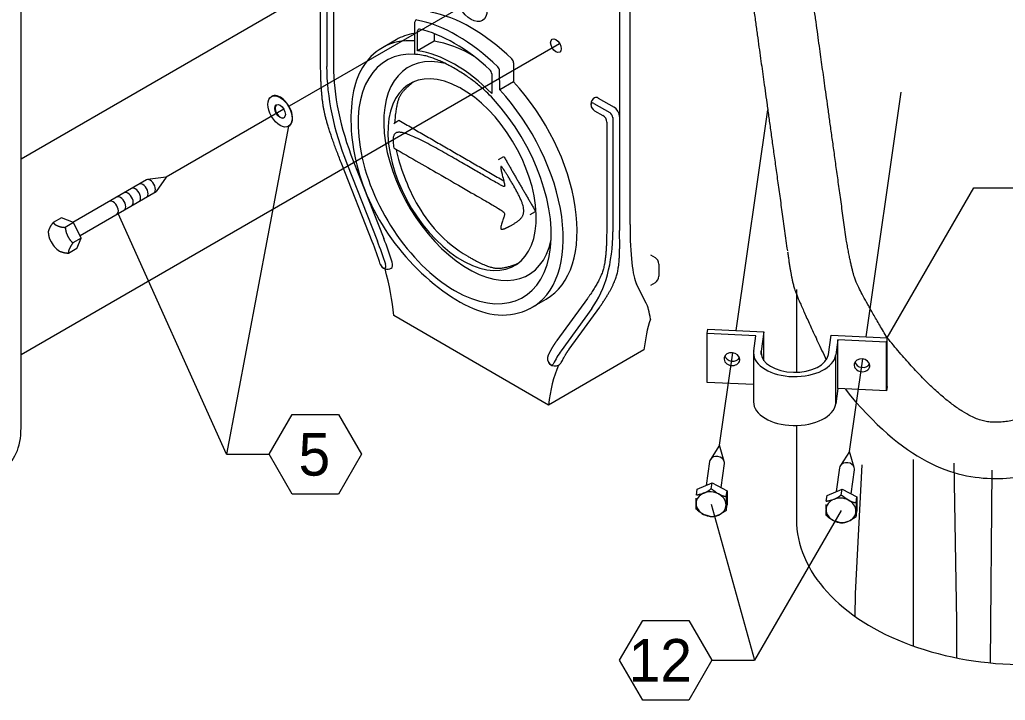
# Model space of a CAD drawing. Extents: x 99862 to 103151, y 100000 to 105076.
# Drawn here: x 101157.1 to 101527.1, y 103346.2 to 103601.7 of the extents above; entities that cross this region are included whole.
import ezdxf

# ---------------------------------------------------------------- set-up
doc = ezdxf.new("R2010")
doc.units = 0
for name, color, linetype in [('Level 15', 7, 'Continuous'), ('Level 16', 7, 'Continuous'), ('Level 20', 7, 'Continuous'), ('Level 28', 7, 'Continuous'), ('Level 31', 7, 'Continuous'), ('Level 33', 7, 'Continuous'), ('Level 34', 7, 'Continuous'), ('Level 35', 7, 'Continuous'), ('Level 36', 7, 'Continuous'), ('Level 38', 7, 'Continuous'), ('Level 41', 7, 'Continuous'), ('Level 42', 7, 'Continuous')]:
    doc.layers.add(name, color=color, linetype=linetype)

msp = doc.modelspace()

# ---------------------------------------------------------------- linework, layer by layer
at = {"layer": 'Level 15'}
for p, q in [((101258.03, 103561.71), (101234.74, 103438.58)), ((101482.7, 103482.36), (101515.2, 103538.65)), ((101515.2, 103538.65), (101531.2, 103538.65)), ((101234.74, 103438.58), (101194.04, 103528.95)), ((101234.74, 103438.58), (101250.74, 103438.58)), ((101416.61, 103419.87), (101432.9, 103361.25)), ((101465.4, 103417.54), (101432.9, 103361.25)), ((101416.9, 103361.25), (101432.9, 103361.25))]:
    msp.add_line(p, q, dxfattribs=at)
at = {"layer": 'Level 16'}
for p, q in [((101157.59, 103549.52), (101296.13, 103629.51)), ((101330.41, 103610.93), (101258.17, 103569.23)), ((101157.59, 103476.04), (101359.77, 103592.77)), ((101474.77, 103482.74), (101487.95, 103574.52)), ((101256.22, 103568.1), (101212, 103542.57)), ((101425.97, 103485.07), (101437.88, 103567.94)), ((101419.78, 103441.97), (101424.77, 103476.71)), ((101468.58, 103439.63), (101473.57, 103474.38))]:
    msp.add_line(p, q, dxfattribs=at)
at = {"layer": 'Level 20'}
for points in [[(101250.74, 103438.58), (101259.4, 103453.57), (101276.72, 103453.57), (101285.37, 103438.58), (101276.72, 103423.58), (101259.4, 103423.58), (101250.74, 103438.58)], [(101382.28, 103361.25), (101390.94, 103376.24), (101408.26, 103376.24), (101416.9, 103361.25), (101408.26, 103346.25), (101390.94, 103346.25), (101382.28, 103361.25)]]:
    msp.add_lwpolyline(points, dxfattribs=at)
at = {"layer": 'Level 28'}
for p, q in [((101415.19, 103483.96), (101415.43, 103485.58)), ((101415.43, 103485.58), (101436.45, 103484.57)), ((101433.41, 103483.09), (101415.19, 103483.96)), ((101415.19, 103465.59), (101415.19, 103483.96)), ((101432.6, 103477.42), (101433.41, 103483.09)), ((101436.45, 103484.57), (101435.4, 103477.29)), ((101436.45, 103473.72), (101436.45, 103484.57)), ((101460.63, 103476.08), (101461.67, 103483.36)), ((101461.67, 103483.36), (101482.7, 103482.36)), ((101482.7, 103482.36), (101482.46, 103480.74)), ((101482.7, 103463.99), (101482.7, 103482.36)), ((101464.24, 103481.61), (101463.43, 103475.95)), ((101482.46, 103480.74), (101464.24, 103481.61)), ((101464.24, 103463.24), (101464.24, 103481.61)), ((101482.46, 103462.37), (101482.46, 103480.74)), ((101432.55, 103476.69), (101432.55, 103458.31)), ((101435.4, 103476.08), (101435.4, 103477.29)), ((101463.43, 103457.58), (101463.43, 103475.95)), ((101432.55, 103464.76), (101415.19, 103465.59)), ((101482.7, 103463.99), (101482.46, 103462.37)), ((101464.24, 103463.24), (101463.43, 103457.58)), ((101482.46, 103462.37), (101464.24, 103463.24)), ((101419.78, 103441.97), (101416.36, 103436.66)), ((101421.58, 103435.91), (101419.78, 103441.97)), ((101468.58, 103439.63), (101465.15, 103434.32)), ((101470.37, 103433.58), (101468.58, 103439.63)), ((101416.07, 103435.89), (101414.78, 103426.91)), ((101420.35, 103426.1), (101421.64, 103435.09)), ((101464.86, 103433.56), (101463.57, 103424.57)), ((101469.14, 103423.77), (101470.43, 103432.76)), ((101411.39, 103425.47), (101416.99, 103427.85)), ((101416.68, 103425.68), (101416.99, 103427.85)), ((101416.99, 103427.85), (101422.6, 103424.93)), ((101411.08, 103423.29), (101411.39, 103425.47)), ((101422.29, 103422.76), (101422.6, 103424.93)), ((101422.6, 103424.93), (101422.6, 103419.63)), ((101459.87, 103420.96), (101460.18, 103423.13)), ((101460.18, 103423.13), (101465.79, 103425.51)), ((101465.48, 103423.34), (101465.79, 103425.51)), ((101465.79, 103425.51), (101471.39, 103422.59)), ((101422.29, 103417.45), (101422.6, 103419.63)), ((101471.08, 103420.42), (101471.39, 103422.59)), ((101471.39, 103422.59), (101471.39, 103417.29)), ((101471.08, 103415.12), (101471.39, 103417.29))]:
    msp.add_line(p, q, dxfattribs=at)
for centre, major_axis, ratio, start_param, end_param in [((101424.43, 103474.33), (2.92, -0.42), 0.813704, 3.141593, 6.283185), ((101424.43, 103474.33), (2.92, -0.42), 0.813704, 0.116344, 3.141593), ((101424.66, 103475.95), (-2.92, 0.42), 0.813704, 0.346937, 2.794655), ((101448.02, 103476.69), (15.47, 0), 0.57735, 3.058857, 3.141593), ((101448.02, 103476.69), (15.47, 0), 0.57735, 3.141593, 6.20045), ((101448.02, 103476.69), (-12.66, 0), 0.57735, 6.20045, 6.283185), ((101448.02, 103476.69), (-12.66, 0), 0.57735, 0, 3.058857), ((101473.23, 103472), (2.92, -0.42), 0.813704, 0.116344, 3.141593), ((101424.43, 103474.33), (2.92, -0.42), 0.813704, 0, 0.116344), ((101473.23, 103472), (2.92, -0.42), 0.813704, 3.141593, 6.283185), ((101473.46, 103473.61), (-2.92, 0.42), 0.813704, 0.346937, 2.794655), ((101473.23, 103472), (2.92, -0.42), 0.813704, 6.283185, 6.399529), ((101448.02, 103458.31), (15.47, 0), 0.57735, 3.141593, 6.20045), ((101418.85, 103435.49), (-2.78, 0.4), 0.813704, 3.499123, 5.925655), ((101418.85, 103435.49), (-2.78, 0.4), 0.813704, 5.925655, 6.283185), ((101418.85, 103435.49), (-2.78, 0.4), 0.813704, 3.141593, 3.499123), ((101467.65, 103433.16), (-2.78, 0.4), 0.813704, 5.925655, 6.283185), ((101467.65, 103433.16), (-2.78, 0.4), 0.813704, 3.499123, 5.925655), ((101467.65, 103433.16), (-2.78, 0.4), 0.813704, 3.141593, 3.499123), ((101416.61, 103419.87), (-5.57, 0.8), 0.813704, 5.352332, 6.399529), ((101416.61, 103419.87), (-5.57, 0.8), 0.813704, 4.305134, 5.352332), ((101416.61, 103419.87), (-5.57, 0.8), 0.813704, 3.257937, 4.305134), ((101416.61, 103419.87), (5.57, -0.8), 0.813704, 3.257937, 4.305134), ((101416.61, 103419.87), (-5.57, 0.8), 0.813704, 2.210739, 3.257937), ((101465.4, 103417.54), (-5.57, 0.8), 0.813704, 5.352332, 6.399529), ((101465.4, 103417.54), (-5.57, 0.8), 0.813704, 4.305134, 5.352332), ((101465.4, 103417.54), (-5.57, 0.8), 0.813704, 3.257937, 4.305134), ((101416.61, 103419.87), (-5.57, 0.8), 0.813704, 1.163542, 2.210739), ((101465.4, 103417.54), (5.57, -0.8), 0.813704, 3.257937, 4.305134), ((101465.4, 103417.54), (-5.57, 0.8), 0.813704, 2.210739, 3.257937), ((101465.4, 103417.54), (-5.57, 0.8), 0.813704, 1.163542, 2.210739)]:
    msp.add_ellipse(centre, major_axis=major_axis, ratio=ratio, start_param=start_param, end_param=end_param, dxfattribs=at)
for points in [[(101411.08, 103423.29), (101411.87, 103423.48), (101412.66, 103423.66), (101413.45, 103423.84)], [(101413.81, 103423.98), (101414.8, 103424.43), (101415.76, 103424.99), (101416.68, 103425.68)], [(101416.68, 103425.68), (101417.47, 103425.09), (101418.27, 103424.5), (101419.06, 103423.91)], [(101419.41, 103423.72), (101420.41, 103423.22), (101421.37, 103422.9), (101422.29, 103422.76)], [(101422.29, 103422.76), (101422.26, 103421.71), (101422.24, 103420.66), (101422.22, 103419.6)], [(101462.6, 103421.65), (101463.6, 103422.09), (101464.56, 103422.65), (101465.48, 103423.34)], [(101465.48, 103423.34), (101466.27, 103422.75), (101467.06, 103422.16), (101467.85, 103421.57)], [(101411, 103420.14), (101411.01, 103420.78), (101411.03, 103421.42), (101411.04, 103422.06)], [(101411.08, 103417.99), (101411.05, 103418.65), (101411.03, 103419.3), (101411, 103419.96)], [(101422.22, 103419.6), (101422.23, 103419), (101422.25, 103418.39), (101422.27, 103417.78)], [(101459.8, 103417.81), (101459.81, 103418.45), (101459.82, 103419.09), (101459.83, 103419.73)], [(101459.87, 103420.96), (101460.66, 103421.14), (101461.45, 103421.32), (101462.25, 103421.51)], [(101468.21, 103421.38), (101469.2, 103420.88), (101470.16, 103420.56), (101471.08, 103420.42)], [(101471.08, 103420.42), (101471.06, 103419.37), (101471.03, 103418.32), (101471.01, 103417.27)], [(101413.81, 103416.03), (101412.82, 103416.57), (101411.9, 103417.22), (101411.08, 103417.99)], [(101416.68, 103415.07), (101415.84, 103415.33), (101415, 103415.59), (101414.16, 103415.85)], [(101419.41, 103415.76), (101418.42, 103415.36), (101417.51, 103415.13), (101416.68, 103415.07)], [(101422.29, 103417.45), (101421.45, 103416.94), (101420.61, 103416.43), (101419.77, 103415.92)], [(101459.87, 103415.65), (101459.85, 103416.31), (101459.82, 103416.97), (101459.8, 103417.62)], [(101462.6, 103413.69), (101461.61, 103414.23), (101460.7, 103414.88), (101459.87, 103415.65)], [(101471.01, 103417.27), (101471.03, 103416.66), (101471.04, 103416.05), (101471.06, 103415.44)], [(101465.48, 103412.73), (101464.64, 103413), (101463.8, 103413.26), (101462.96, 103413.52)], [(101468.21, 103413.43), (101467.22, 103413.02), (101466.3, 103412.79), (101465.48, 103412.73)], [(101471.08, 103415.12), (101470.24, 103414.61), (101469.4, 103414.1), (101468.56, 103413.59)]]:
    msp.add_open_spline(points, degree=2, dxfattribs=at)
at = {"layer": 'Level 31'}
for p, q in [((101448.67, 103500.4), (101448.67, 103469.39)), ((101448.67, 103449.39), (101448.67, 103414.17))]:
    msp.add_line(p, q, dxfattribs=at)
for points in [[(101470.74, 103377.68), (101470.85, 103386.36), (101473.31, 103434.61)], [(101492.6, 103366.59), (101492.6, 103436.63)], [(101508.82, 103362.16), (101508.92, 103375.77), (101507.85, 103435.25)], [(101521.55, 103360.28), (101522.11, 103432.65)]]:
    msp.add_lwpolyline(points, dxfattribs=at)
msp.add_ellipse((101534.5, 103414.17), major_axis=(85.83, 0), ratio=0.635085, start_param=3.14158, end_param=6.283185, dxfattribs=at)
at = {"layer": 'Level 33'}
for p, q in [((101382.23, 103697.07), (101382.23, 103565.4)), ((101386.21, 103524.84), (101386.21, 103699.36)), ((101270.04, 103585.69), (101270.04, 103628.55)), ((101272.31, 103624.4), (101272.31, 103584.1)), ((101274.84, 103622.81), (101274.84, 103584.54)), ((101305.29, 103600.29), (101305.29, 103589.02)), ((101306.42, 103590.05), (101306.42, 103597.51)), ((101312.63, 103596.52), (101312.63, 103593.63)), ((101298.42, 103594.22), (101293.22, 103591.22)), ((101312.63, 103593.63), (101306.42, 103590.05)), ((101342.46, 103585.54), (101342.46, 103578.41)), ((101337.26, 103575.41), (101337.25, 103582.53)), ((101334.26, 103581.43), (101334.26, 103573.98)), ((101342.46, 103578.41), (101337.26, 103575.41)), ((101374.28, 103572.29), (101380.24, 103568.85)), ((101372.62, 103570.32), (101378.59, 103566.87)), ((101372.87, 103567.56), (101376.02, 103565.74)), ((101377.43, 103563.3), (101377.43, 103523.69)), ((101379.7, 103564.96), (101379.7, 103522.1)), ((101382.23, 103565.4), (101382.23, 103522.54)), ((101282.29, 103548.74), (101293.77, 103519.64)), ((101289.45, 103518.41), (101277.97, 103547.51)), ((101279.88, 103547.7), (101291.36, 103518.61)), ((101393.84, 103513.45), (101395.57, 103512.45)), ((101396.98, 103510.01), (101396.98, 103505.42)), ((101392.27, 103495.37), (101388.65, 103502.49)), ((101395.57, 103502.99), (101393.84, 103501.99)), ((101349.47, 103493.79), (101354.67, 103496.79)), ((101370.24, 103497.13), (101358.76, 103481.29)), ((101371.82, 103493.32), (101360.34, 103477.48)), ((101363.32, 103477.99), (101374.8, 103493.83)), ((101355.63, 103457.08), (101297.46, 103490.66)), ((101391.43, 103477.74), (101355.63, 103457.08))]:
    msp.add_line(p, q, dxfattribs=at)
for centre, radius, start, end in [((101374.28, 103569.99), 2.81, 120, 240), ((101374.62, 103563.3), 2.81, 360, 60), ((101394.16, 103510.01), 2.81, 0, 60), ((101295.09, 103510.81), 2.79, 197.7565, 251.962), ((101295.09, 103510.81), 2.79, 251.962, 300.4656), ((101394.16, 103505.42), 2.81, 300, 0), ((101358, 103474.53), 2.81, 154.0815, 299.6218), ((101358, 103474.53), 2.81, 299.6218, 328.2181)]:
    msp.add_arc(centre, radius, start, end, dxfattribs=at)
for centre, major_axis in [((101326.55, 103608.7), (-4.22, 7.31)), ((101358.37, 103591.95), (-1.41, 2.44))]:
    msp.add_ellipse(centre, major_axis=major_axis, ratio=0.57735, dxfattribs=at)
for centre, major_axis, ratio, start_param, end_param in [((101326.55, 103543.58), (-33.75, 58.46), 0.57735, 5.172956, 5.822618), ((101306.33, 103600.45), (0.26, 1.38), 0.731418, 0.561152, 1.823018), ((101321.34, 103540.58), (33.75, -58.46), 0.57735, 2.031363, 2.681026), ((101326.55, 103545.5), (-28.13, 48.71), 0.57735, 6.069803, 6.28319), ((101307.42, 103596.93), (0.7, -1.22), 0.57735, 2.649261, 3.926991), ((101320.34, 103540), (32.34, -56.02), 0.57735, 2.063128, 2.649261), ((101321.35, 103542.5), (28.13, -48.71), 0.57735, 2.771884, 3.141593), ((101326.55, 103543.58), (-27.55, 47.71), 0.57735, 5.467511, 5.86323), ((101320.35, 103541.93), (25.65, -44.43), 0.57735, 2.770312, 8.225262), ((101320.34, 103540), (27.55, -47.71), 0.57735, 1.990752, 2.721637), ((101305.44, 103588.93), (0.107, -0.186), 0.57735, 3.926991, 5.90159), ((101341.46, 103586.12), (-0.7, 1.22), 0.57735, 3.926991, 5.172956), ((101326.88, 103552.59), (-38.59, 66.84), 0.57735, 0.785398, 1.318407), ((101328.54, 103553.54), (37.97, -65.76), 0.57735, 3.926991, 4.46), ((101333.27, 103582.01), (0.7, -1.22), 0.57735, 0.785398, 2.063128), ((101336.25, 103583.11), (-0.7, 1.22), 0.57735, 3.926991, 5.172956), ((101326.55, 103545.5), (-28.13, 48.71), 0.57735, 3.141593, 5.08627), ((101321.35, 103542.5), (28.13, -48.71), 0.57735, 6.254516, 8.227863), ((101374.28, 103569.99), (-1.41, 2.44), 0.57735, 5.497787, 6.283185), ((101372.62, 103569.04), (0.78, -1.36), 0.57735, 2.356194, 5.497787), ((101380.24, 103566.55), (-1.41, 2.44), 0.57735, 3.926991, 5.497787), ((101378.59, 103565.59), (0.78, -1.36), 0.57735, 0.785398, 2.356194), ((101403.79, 103599.29), (-13.48, -98.36), 0.114691, 5.586537, 6.119546), ((101244.09, 103514.48), (-40.78, 70.64), 0.57735, 4.339992, 4.46), ((101322.91, 103554.88), (40.16, -69.56), 0.57735, 0.252389, 0.785398), ((101292.05, 103519.47), (2.62, 1.03), 0.203894, 3.101194, 3.181991), ((101242.44, 103513.53), (-38.59, 66.84), 0.57735, 4.339992, 4.46), ((101242.44, 103513.53), (40.16, -69.56), 0.57735, 1.198399, 1.318408), ((101293.44, 103509.89), (0.78, -1.36), 0.57735, 4.712389, 7.481585), ((101242.11, 103515.63), (-39.38, 68.2), 0.57735, 4.035936, 4.286649), ((101295.1, 103510.84), (-1.41, 2.44), 0.57735, 3.141594, 4.339992), ((101377.13, 103398.58), (-13.48, -98.36), 0.114691, 2.760167, 2.977954), ((101446.79, 103438.79), (-39.38, 68.2), 0.57735, 0.470176, 0.676453), ((101407.35, 103418.32), (-38.59, 66.84), 0.57735, 0.252389, 0.372397), ((101356.34, 103473.57), (0.78, -1.36), 0.57735, 4.712389, 6.655582), ((101410.99, 103418.13), (-39.38, 68.2), 0.57735, 0.400156, 0.676453)]:
    msp.add_ellipse(centre, major_axis=major_axis, ratio=ratio, start_param=start_param, end_param=end_param, dxfattribs=at)
for points, degree in [([(101293.22, 103591.22), (101286.74, 103587.18), (101280.3, 103575.69), (101281.72, 103545.48), (101297.31, 103514.82), (101324.44, 103491.58), (101340.95, 103489.25), (101348.85, 103493.44)], 3), ([(101277.96, 103547.53), (101272.8, 103560.58), (101270.03, 103573.87), (101270.04, 103585.69)], 2), ([(101334.95, 103571.85), (101332.65, 103574.3), (101330.25, 103576.51), (101326.59, 103579.37), (101325.37, 103580.24), (101322.95, 103581.84), (101321.75, 103582.58), (101319.25, 103584.02), (101317.95, 103584.72), (101315.41, 103585.99), (101314.16, 103586.55), (101310.48, 103587.93), (101308.07, 103588.49), (101305.76, 103588.71)], 3), ([(101377.43, 103523.69), (101377.45, 103512.72), (101374.85, 103503.44), (101370.24, 103497.13)], 2), ([(101374.8, 103493.83), (101380.24, 103501.68), (101382.58, 103511.31), (101382.23, 103522.54)], 2), ([(101358.76, 103481.29), (101357.53, 103479.59), (101356.43, 103477.74), (101355.47, 103475.76)], 2), ([(101360.39, 103473.05), (101361.89, 103475.88), (101362.58, 103476.97), (101363.32, 103477.99)], 2)]:
    msp.add_open_spline(points, degree=degree, dxfattribs=at)
at = {"layer": 'Level 34'}
for centre, major_axis, start_param, end_param in [((101325.53, 103544.92), (22.5, -38.97), 2.632698, 6.851151), ((101323.14, 103543.54), (19.69, -34.1), 2.394599, 8.675608)]:
    msp.add_ellipse(centre, major_axis=major_axis, ratio=0.57735, start_param=start_param, end_param=end_param, dxfattribs=at)
at = {"layer": 'Level 35'}
for p, q in [((101297.46, 103562.8), (101299.45, 103563.95)), ((101336.78, 103549.28), (101338.77, 103550.43)), ((101348.72, 103528.61), (101350.71, 103529.76))]:
    msp.add_line(p, q, dxfattribs=at)
for points, degree in [([(101299.45, 103563.95), (101319.11, 103552.6), (101338.77, 103541.25)], 2), ([(101297.46, 103553.62), (101296.84, 103558.57), (101297.46, 103562.8), (101317.76, 103551.08), (101338.06, 103539.36), (101339.44, 103538.57), (101339, 103540.33), (101337.89, 103544.81), (101336.78, 103549.28), (101342.75, 103538.95), (101348.72, 103528.61), (101342.75, 103525.17), (101336.78, 103521.73), (101337.89, 103524.92), (101339, 103528.12), (101339.44, 103529.38), (101338.06, 103530.18), (101317.76, 103541.9), (101297.46, 103553.62)], 4), ([(101338.77, 103550.43), (101344.74, 103540.1), (101350.71, 103529.76)], 2)]:
    msp.add_open_spline(points, degree=degree, dxfattribs=at)
at = {"layer": 'Level 36'}
for points, degree in [([(101304.89, 103578.35), (101300.74, 103575.23), (101298.3, 103569.71), (101297.82, 103563.01)], 2), ([(101298.41, 103553.07), (101299.18, 103548.75), (101304.2, 103532.6), (101316.26, 103518.13), (101325.25, 103512.94)], 3), ([(101325.25, 103512.94), (101331.94, 103509.04), (101338.8, 103508.01), (101344.14, 103510.31)], 2)]:
    msp.add_open_spline(points, degree=degree, dxfattribs=at)
at = {"layer": 'Level 38'}
for p, q in [((101204.65, 103541.57), (101177.07, 103525.65)), ((101212, 103542.57), (101204.99, 103541.69)), ((101212, 103542.57), (101208.36, 103537.22)), ((101179.72, 103520.68), (101208.36, 103537.22)), ((101172.78, 103527.38), (101169.63, 103525.56)), ((101177.33, 103525.54), (101172.78, 103527.38)), ((101177.33, 103525.54), (101174.17, 103523.72)), ((101180.19, 103519.74), (101177.33, 103525.54)), ((101180.19, 103519.74), (101177.03, 103517.92)), ((101178.5, 103515.78), (101180.19, 103519.74)), ((101178.5, 103515.78), (101175.35, 103513.96))]:
    msp.add_line(p, q, dxfattribs=at)
for major_axis in [(-3.22, 5.58), (1.41, -2.44)]:
    msp.add_ellipse((101254.81, 103567.29), major_axis=major_axis, ratio=0.57735, dxfattribs=at)
for centre, major_axis, start_param, end_param in [((101254.95, 103567.37), (-3.22, 5.58), 4.16506, 6.304836), ((101254.95, 103567.37), (1.41, -2.44), 3.19121, 6.233568), ((101254.95, 103567.37), (-3.22, 5.58), 3.119941, 4.16506), ((101171.98, 103519.46), (2.81, -4.87), 4.59906, 5.646257)]:
    msp.add_ellipse(centre, major_axis=major_axis, ratio=0.57735, start_param=start_param, end_param=end_param, dxfattribs=at)
for points in [[(101167.95, 103521.6), (101167.91, 103522.05), (101167.99, 103522.6), (101168.28, 103523.28)], [(101168.28, 103523.28), (101168.57, 103523.96), (101169.06, 103524.75), (101169.63, 103525.56)], [(101169.63, 103525.56), (101170.05, 103525.09), (101170.61, 103524.66), (101171.39, 103524.34)], [(101171.39, 103524.34), (101172.17, 103524.03), (101173.14, 103523.84), (101174.17, 103523.72)], [(101174.17, 103523.72), (101174.33, 103522.62), (101174.6, 103521.52), (101175.09, 103520.52)], [(101168.87, 103518.4), (101168.37, 103519.4), (101168.1, 103520.49), (101167.95, 103521.6)], [(101175.09, 103520.52), (101175.58, 103519.53), (101176.27, 103518.67), (101177.03, 103517.92)], [(101175.68, 103515.64), (101175.39, 103514.96), (101175.31, 103514.41), (101175.35, 103513.96)], [(101177.03, 103517.92), (101176.46, 103517.11), (101175.97, 103516.32), (101175.68, 103515.64)], [(101175.35, 103513.96), (101174.32, 103514.07), (101173.35, 103514.26), (101172.57, 103514.58)]]:
    msp.add_open_spline(points, degree=2, dxfattribs=at)
at = {"layer": 'Level 41'}
msp.add_line((101157.59, 103448.48), (101157.59, 103678.49), dxfattribs=at)
for centre, major_axis, start_param, end_param in [((101206.06, 103539.14), (1.41, -2.44), 6.28318, 9.424778), ((101200.48, 103535.92), (1.41, -2.44), 6.28318, 9.424778), ((101203.27, 103537.53), (1.41, -2.44), 6.28318, 9.424778), ((101192.11, 103531.08), (1.41, -2.44), 6.28318, 9.424778), ((101194.9, 103532.69), (1.41, -2.44), 6.28318, 9.424778), ((101197.69, 103534.31), (1.41, -2.44), 6.28318, 9.424778), ((101133.72, 103462.26), (16.88, -29.23), 0, 0.785398)]:
    msp.add_ellipse(centre, major_axis=major_axis, ratio=0.57735, start_param=start_param, end_param=end_param, dxfattribs=at)
at = {"layer": 'Level 42'}
for points, degree in [([(101426.24, 103651.5), (101432.58, 103606.01), (101438.91, 103560.51), (101445.24, 103515.02)], 2), ([(101467.49, 103518.37), (101461.32, 103562.71), (101455.15, 103607.04), (101448.98, 103651.38)], 2), ([(101482.7, 103482.36), (101471.75, 103500.67), (101469.16, 103509.13), (101467.46, 103518.53)], 2), ([(101445.31, 103514.61), (101446.53, 103505.86), (101448.67, 103497.61), (101459.85, 103474.1)], 2), ([(101561.56, 103465.13), (101534.12, 103448.88), (101506.88, 103452.72), (101482.7, 103482.36)], 2), ([(101466.89, 103463.11), (101489.07, 103435.58), (101526.2, 103423.52), (101564.01, 103441.33), (101568.49, 103443.21), (101571.5, 103444.91), (101572.85, 103445.67)], 3)]:
    msp.add_open_spline(points, degree=degree, dxfattribs=at)

# ---------------------------------------------------------------- texts
at = {"layer": 'Level 20'}
for s, p in [('5', (101261.75, 103430.58)), ('12', (101385.66, 103353.25))]:
    msp.add_text(s, height=16, dxfattribs=at).set_placement(p)

doc.saveas('drawing.dxf')
